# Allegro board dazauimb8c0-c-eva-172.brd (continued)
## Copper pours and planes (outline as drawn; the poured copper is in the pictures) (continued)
GND on IN1 (solid shape): outline of 260 points within 0.25,18.86 15.33,29.65
GND on IN1 (solid shape): outline of 1575 points within 0.25,0.25 219.55,127.75
GND on IN2 (solid shape): 102.8,87.87 102.8,85.58 102.68,85.46 98.99,85.46 98.87,85.58 98.87,86.85 98.11,87.62 98.11,88.25 98.27,88.42 102.26,88.42
GND on IN2 (solid shape): 27.16,72.69 27.16,70.36 27.01,70.2 26.97,70.2 26.5,70.2 26.39,70.32 26.39,72.76 27.1,72.76
GND on IN2 (solid shape): 100.64,26.62 100.64,26.16 100.13,25.66 100.13,25.65 99.99,25.51 99.99,25 99.84,24.85 97.3,24.85 96.93,25.22 96.93,25.72 97.51,26.3 97.51,26.38 97.56,26.44 97.56,26.75 97.66,26.84 100.12,26.84 100.16,26.88 100.37,26.88
GND on IN2 (solid shape): 49.18,98.59 49.29,98.61 49.35,98.52 49.35,97.53 49.06,97.24 44.86,97.24 44.76,97.31 44.79,97.42 45.14,97.78 48.36,97.78
GND on IN2 (solid shape): 22.01,69.96 22.01,66.36 19.29,63.64 16.11,63.64 15.3,62.83 15.3,60.54 14.82,60.06 13.67,60.06 13.27,59.65 13.27,59.24 12.5,59.24 12.5,61.84 11.88,62.58 11.04,62.09 8.9,62.09 8.54,61.95 8.4,61.59 8.4,61.49 2.21,61.49 1.85,61.85 1.85,67.89 2.21,68.25 7.07,68.25 8.33,67.35 9.35,68.5 9.35,70.8 9.49,70.93 9.74,70.93 9.82,70.85 9.82,70.27 10.15,69.94 12.91,69.94 15.66,72.68 19.29,72.68
GND on IN2 (solid shape): 12.42,89.2 12.37,88.88 12.25,88.59 12.25,87.74 12.71,87.28 12.71,83.2 12.03,82.51 10.63,82.51 9.97,81.85 9.43,81.85 9.35,81.93 9.35,83.9 8.33,85.05 7.07,84.15 2.11,84.15 1.75,84.51 1.75,87.15 0.25,87.15 0.25,88.4 0.61,88.75 4.75,88.75 4.75,88 4.88,87.68 5.2,87.55 6.6,87.55 6.92,87.68 7.05,88 7.05,88.75 11.2,88.75 11.52,88.88 11.65,89.2 11.65,89.6 12.42,89.6
GND on IN2 (solid shape): 13.27,49.39 14.08,48.58 14.72,48.58 15.07,48.22 15.07,47.64 14.67,47.23 13.65,47.23 13.24,46.82 13.24,45.33 14.73,43.84 14.73,42.51 15.3,41.94 15.3,40.27 15.05,40.02 13.54,40.02 13.27,39.74 13.27,39.25 12.5,39.25 12.5,41.84 11.88,42.58 11.04,42.09 8.9,42.09 8.54,41.95 8.4,41.59 8.4,41.49 3.35,41.49 2.99,41.85 2.99,47.03 3.35,47.39 8.4,47.39 8.4,47.29 8.54,46.93 8.9,46.79 11.04,46.79 11.88,46.3 12.5,47.04 12.5,49.62 13.27,49.62
GND on IN2 (solid shape): 10.37,113.92 10.43,113.83 10.43,113.55 10.73,113.24 13.17,113.24 15.48,110.93 15.48,107.4 12.38,104.3 12.38,103.5 12.41,103.35 12.42,103.2 12.42,102.5 11.65,102.5 11.65,103.2 11.52,103.52 11.2,103.65 7.05,103.65 7.05,104.4 6.92,104.72 6.6,104.85 5.2,104.85 4.88,104.72 4.75,104.4 4.75,103.65 0.61,103.65 0.25,104.01 0.25,105.29 0.41,105.45 1.85,105.45 1.85,110.95 0.41,110.95 0.25,111.11 0.25,112.69 0.61,113.05 3.35,113.05 3.41,113.03 3.69,112.81 3.97,112.75 5.93,112.75 6.22,112.82 6.5,113.05 7.44,113.08 7.45,113.05 8.34,112.73 8.62,113.64 8.62,113.75 8.72,113.79 8.78,113.78 8.84,113.78 9.86,113.78 10.07,113.81 10.26,113.91
GND on IN2 (solid shape): 46.78,105.13 46.78,103.72 47.83,102.68 47.83,102.38 47.78,102.3 47.69,102.29 47.63,102.3 47.56,102.31 47.3,102.2 47.19,101.94 47.22,101.81 47.29,101.69 47.31,101.62 47.29,101.56 47.22,101.44 47.19,101.31 47.3,101.05 47.56,100.94 47.65,100.95 47.76,100.99 47.81,100.98 47.83,100.94 47.83,100.9 47.23,100.3 46.3,100.3 46.22,100.35 46.21,100.45 46.24,100.53 46.25,100.62 46.17,100.85 45.96,100.98 45.9,101.03 45.88,101.11 45.89,101.16 45.9,101.2 45.89,101.26 45.88,101.33 45.88,101.58 45.91,101.61 45.98,101.64 46.05,101.62 46.16,101.55 46.29,101.53 46.56,101.63 46.66,101.9 46.6,102.09 46.45,102.23 46.39,102.3 46.42,102.39 46.58,102.56 46.58,105 46.66,105.08 46.66,105.09 46.72,105.16
GND on IN2 (solid shape): outline of 173 points within 48.13,101.58 51.72,104.62
GND on IN2 (solid shape): outline of 260 points within 0.25,18.86 15.28,29.65
GND on IN2 (solid shape): outline of 1570 points within 0.25,0.25 219.55,127.75
GND on IN2 (solid shape): outline of 29993 points within 28.68,30.44 80.96,95.39
GND on SVCC (solid shape): 218.28,51.43 217.55,50.87 217.28,50 217.28,48.84 216.81,48.37 216.32,48.37 215.96,48.73 215.96,49.64 215.94,49.74 215.89,49.82 215.38,50.33 215.3,50.39 215.2,50.41 212.89,50.41 212.79,50.51 212.79,50.79 212.78,50.84 214.4,53.59 215.76,56.48 218.28,56.48
GND on SVCC (solid shape): 7.57,46.12 8.17,45.67 8.9,45.52 10.42,45.52 11.04,45.15 11.75,45.02 11.75,43.86 11.04,43.73 10.42,43.36 8.9,43.36 8.17,43.21 7.57,42.76 4.64,42.76 4.26,43.14 4.26,45.63 4.75,46.12
GND on SVCC (solid shape): 123.18,126.4 123.77,124.97 125.2,124.38 131.2,124.38 132.63,124.97 133.22,126.4 133.22,126.48 143.48,126.48 143.48,124.99 143.42,124.9 143.32,124.9 142.93,125.07 142.5,125.13 141.35,124.65 140.87,123.5 141.35,122.35 142.5,121.87 142.93,121.93 143.32,122.1 143.42,122.1 143.48,122.01 143.48,81.78 143.21,81.52 142.13,81.52 142.03,81.57 141.92,81.58 141.82,81.57 141.73,81.53 141.71,81.52 141.59,81.52 141.58,81.55 141.44,81.72 141.24,81.79 141.03,81.72 140.89,81.55 140.88,81.52 126.41,81.52 123.51,84.42 123.51,85.58 123.49,85.68 123.43,85.76 121.02,88.18 120.94,88.23 120.84,88.25 111.55,88.25 110.04,89.75 110.04,91.05 110.02,91.14 109.97,91.22 107.96,93.24 107.95,93.26 107.86,93.44 107.68,93.53 107.66,93.53 106.62,94.58 106.62,95.8 106.62,95.85 106.62,95.91 106.62,96.29 107.08,96.76 109.54,96.76 109.63,96.78 109.72,96.83 110.1,97.22 110.15,97.3 110.17,97.4 110.17,114.05 114.92,118.81 114.98,118.89 115,118.99 115,125.86 115.61,126.48 123.18,126.48
GND on SVCC (solid shape): outline of 145 points within 26.61,34.28 82.74,96.38
GND on IN3 (solid shape): 65.85,37.19 65.85,34.53 65.71,34.4 65.71,33.88 63.94,33.88 63.94,37.32 65.72,37.32
GND on IN3 (solid shape): 100.77,26.91 100.77,26.15 100.26,25.64 100.26,24.88 100.14,24.75 97.47,24.75 97.09,25.13 97.09,27.04 97.34,27.29 100.39,27.29
GND on IN3 (solid shape): 102.8,88.12 102.8,85.46 102.55,85.2 98.99,85.2 98.87,85.33 98.87,86.98 98.23,87.62 98.23,88.12 98.49,88.38 102.55,88.38
GND on IN3 (solid shape): 45.73,113.78 45.73,112.46 45.63,112.36 44,112.36 43.8,112.56 43.8,113.37 43.7,113.47 43.09,113.47 42.99,113.57 42.99,113.78 43.09,113.88 45.63,113.88
GND on IN3 (solid shape): 12.42,89.2 12.37,88.88 12.25,88.59 12.25,87.74 12.71,87.28 12.71,83.2 12.03,82.51 10.63,82.51 9.94,81.82 9.51,81.82 9.35,81.98 9.35,83.9 8.33,85.05 7.07,84.15 2.11,84.15 1.75,84.51 1.75,87.15 0.25,87.15 0.25,88.4 0.61,88.75 4.73,88.75 4.75,88.73 4.75,88 4.88,87.68 5.2,87.55 6.6,87.55 6.92,87.68 7.05,88 7.05,88.75 11.2,88.75 11.52,88.88 11.65,89.2 11.65,89.6 12.42,89.6
GND on IN3 (solid shape): 13.27,49.39 14.08,48.58 14.72,48.58 15.07,48.22 15.07,47.64 14.67,47.23 13.65,47.23 13.52,47.1 13.52,45.58 14.08,45.02 14.08,42.35 15.3,41.13 15.3,40.27 15.05,40.02 13.54,40.02 13.27,39.74 13.27,39.25 12.5,39.25 12.5,41.84 11.88,42.58 11.04,42.09 8.9,42.09 8.54,41.95 8.4,41.59 8.4,41.49 3.35,41.49 2.99,41.85 2.99,47.03 3.35,47.39 8.4,47.39 8.4,47.29 8.54,46.93 8.9,46.79 11.04,46.79 11.88,46.3 12.5,47.04 12.5,49.62 13.27,49.62
GND on IN3 (solid shape): 21.53,69.8 21.59,69.64 21.64,69.47 21.64,66.83 21.61,66.74 21.58,66.65 18.98,64.05 18.7,63.95 18.4,63.88 16.36,63.88 15.3,62.83 15.3,60.54 14.82,60.06 13.67,60.06 13.27,59.65 13.27,59.24 12.5,59.24 12.5,61.84 11.88,62.58 11.04,62.09 8.9,62.09 8.54,61.95 8.4,61.59 8.4,61.49 2.21,61.49 1.85,61.85 1.85,67.89 2.21,68.25 7.07,68.25 8.33,67.35 9.35,68.5 9.35,70.85 9.46,70.95 9.74,70.95 9.82,70.88 9.82,70.27 10.15,69.94 13.58,69.94 15.65,72.01 19.31,72.01
GND on IN3 (solid shape): 10.73,113.24 13.17,113.24 15.48,110.93 15.48,107.4 12.38,104.3 12.38,103.5 12.41,103.35 12.42,103.2 12.42,102.5 11.65,102.5 11.65,103.2 11.52,103.52 11.2,103.65 7.05,103.65 7.05,104.4 6.92,104.72 6.6,104.85 5.2,104.85 4.88,104.72 4.75,104.4 4.75,103.65 0.61,103.65 0.25,104.01 0.25,105.29 0.41,105.45 1.85,105.45 1.85,110.95 0.41,110.95 0.25,111.11 0.25,112.69 0.61,113.05 3.35,113.05 3.41,113.03 3.69,112.81 3.97,112.75 5.93,112.75 6.22,112.82 6.5,113.05 7.44,113.08 7.45,113.05 8.19,112.67 8.7,113.33 8.89,113.51 10.46,113.51
GND on IN3 (solid shape): outline of 260 points within 0.25,18.86 15.33,29.65
GND on IN3 (solid shape): outline of 1592 points within 0.25,0.25 219.55,127.75
GND on SGND1 (solid shape): outline of 2645 points within 0.51,0.51 219.29,127.49
V3A_BOOT on BOTTOM (solid shape): 147.51,32.93 147.51,32.63 147.18,32.29 147.18,31.94 147.15,31.91 147.13,31.91 147.1,31.89 146.39,31.89 146.34,31.94 146.34,32.22 146.42,32.29 146.57,32.29 146.72,32.45 146.72,32.93 146.77,32.98 147.46,32.98
VCC1P8A on TOP (solid shape): outline of 383 points within 93.55,51.37 108.8,58.08
VCCPLL_OC_DIS2 on TOP (solid shape): 52.51,30.47 52.51,29.7 52.39,29.57 52.39,29.34 52.33,29.25 52.23,29.25 51.74,29.17 51.78,28.67 51.81,28.6 51.78,28.52 51.65,28.39 51.65,28.22 51.6,28.13 51.5,28.13 51.37,28.25 51.19,28.3 50.99,28.24 50.86,28.08 50.84,28.05 49.67,28.05 49.5,28.22 49.5,28.6 49.92,29.02 50.2,29.02 50.61,29.42 50.61,30.59 50.73,30.72 52.26,30.72
VCCSTPLL_DIS2 on BOTTOM (solid shape): 112.74,59.65 112.74,58.81 112.71,58.79 112.08,58.79 111.62,58.33 111.55,58.32 111.48,58.3 110.44,58.3 110.41,58.28 110.35,58.28 110.35,59.63 111.89,59.63 111.95,59.6 112.05,59.59 112.15,59.6 112.2,59.6 112.3,59.7 112.69,59.7
VDDQ_SW on TOP (solid shape): 59.77,124.12 59.77,123.66 60.75,122.69 60.75,122.61 62.16,121.2 64.8,121.2 64.86,121.14 64.86,120.97 64.84,120.95 63.61,120.95 63.35,120.68 61.92,120.68 61.87,120.69 61.83,120.69 61.79,120.69 61.74,120.68 61.57,120.68 61.48,120.59 57.36,120.59 57.21,120.74 57.21,123.94 57.45,124.19 59.7,124.19
VDDQ_SW on BOTTOM (solid shape): 61.54,121.68 61.54,120.66 61.38,120.51 60.71,120.51 60.4,120.82 60.4,121.04 60.21,121.23 59.76,121.23 59.67,121.32 59.67,122.15 60.1,122.58 60.65,122.58
VDDQ_SW_VPP on TOP (solid shape): 63.31,125.68 63.31,123.59 63.19,123.47 63.19,122.74 63.14,122.74 63.14,122.2 63.12,122.18 62.43,122.18 62.16,122.44 62.16,123.21 62.15,123.22 62.15,125.7 63.28,125.7
VDDQ_VCC on TOP (solid shape): 67.39,125.06 67.39,124.4 67,124.01 66.46,124.01 66.18,123.73 64.54,123.73 64.26,123.45 64.26,122.74 64.14,122.74 64.14,122.17 63.89,122.17 63.89,122.74 63.64,122.74 63.64,122.17 63.41,122.17 63.39,122.18 63.39,122.74 63.35,122.74 63.35,123.25 63.54,123.44 63.54,124.4 63.73,124.58 66.45,124.58 67,125.13 67.32,125.13
VDDQ_VLDOIN on TOP (solid shape): 61.62,119.93 62.05,119.93 62.14,120.02 63.04,120.02 63.1,119.96 63.1,119.36 62.94,119.19 62.29,119.19 62.25,119.2 62.21,119.2 62.17,119.2 62.13,119.19 62,119.19 61.73,118.93 61.73,118.03 61.6,117.89 61.17,117.89 60.79,118.27 60.79,119.83 60.98,120.02 61.53,120.02
VDDQ_VTT on TOP (solid shape): 63.64,119.9 63.64,119.34 63.67,119.34 63.67,119.02 63.54,118.89 63.54,118.73 63.38,118.57 63.38,118 63.29,117.91 62.95,117.91 62.84,118.02 62.84,118.85 63.33,119.34 63.39,119.34 63.39,119.92 63.62,119.92
VDDQ_VTT on BOTTOM (solid shape): 64.19,121.41 64.19,120.35 63.99,120.14 63.99,119.39 63.6,119 63.6,118.65 63.55,118.59 62.86,118.59 62.86,120.33 63.14,120.6 63.14,121.24 63.14,121.24 63.41,121.51 64.09,121.51
5213LX_1.8V on TOP (solid shape): 40.02,32.02 40.02,31.63 39.84,31.46 39.74,31.46 39.56,31.28 39.56,30.69 39.48,30.62 39.48,30.29 39.51,30.26 39.51,30.1 39.52,30.07 39.53,30.03 39.64,30.03 39.64,30.03 40.53,30.03 40.53,30.02 40.53,29.73 40.35,29.73 40.35,29.73 39.58,29.73 39.18,29.32 39.18,28.82 38.67,28.31 38.03,28.31 37.91,28.43 37.91,31.86 38.16,32.12 39.91,32.12
8813BOOT1 on TOP (solid shape): 77.94,114.54 77.97,114.53 77.99,114.49 77.99,113.96 77.97,113.92 77.94,113.91 77.48,113.91 75.91,112.33 75.2,112.33 75.09,112.43 75.09,113.12 75.14,113.17 75.83,113.17 77.2,114.54
8813BOOT2 on TOP (solid shape): 76.97,108.32 78.29,108.32 78.42,108.19 78.42,107.56 78.29,107.43 78.22,107.43 77.63,107.43 77.59,107.43 76.52,107.43 75.55,108.39 75.09,108.39 75.08,108.41 75.08,109.09 75.21,109.22 76.07,109.22
8813LGAT1 on TOP (solid shape): 77.94,112.03 77.94,111.62 77.71,111.39 75.6,111.39 75.57,111.41 75.55,111.44 75.55,111.63 75.57,111.67 75.6,111.68 76.37,111.68 76.37,111.7 76.44,111.7 77.05,112.3 77.66,112.3
8813LGAT1 on BOTTOM (solid shape): 77.33,117.33 77.33,116.7 77.31,116.66 77.28,116.65 76.8,116.65 76.41,116.27 76.41,116.14 76.24,115.96 75.35,115.96 75.3,115.91 75.3,115.61 75.25,115.56 74.84,115.56 74.76,115.63 74.76,116.19 75.04,116.47 75.04,117.56 75.14,117.66 77,117.66
8813LGAT2 on BOTTOM (solid shape): 84.06,110.02 84.06,109.66 84.02,109.57 84.01,109.46 84.02,109.35 84.06,109.26 84.06,107.83 83.98,107.76 83.32,107.76 83.22,107.86 83.22,110.1 83.42,110.3 83.78,110.3
8813PHASE1 on TOP (solid shape): 77.96,113.22 78,113.2 78.01,113.17 78.01,112.56 77.99,112.53 77.02,112.53 76.39,111.9 75.6,111.9 75.57,111.91 75.55,111.95 75.55,112.08 75.65,112.18 75.93,112.18 75.96,112.2 76.98,113.22
8813PHASE1 on BOTTOM (solid shape): 79.79,121.98 79.79,117.66 79.54,117.41 77.76,117.41 77.1,118.07 76.29,118.07 75.96,118.4 75.96,121.25 76.8,122.08 79.69,122.08
8813PHASE2 on TOP (solid shape): 76.46,109.66 76.72,109.66 76.92,109.46 77.36,109.46 78.29,109.46 78.42,109.33 78.42,108.83 78.29,108.7 76.8,108.7 76.11,109.38 75.65,109.38 75.55,109.49 75.55,109.59 75.63,109.66 76.46,109.66
8813PHASE2 on BOTTOM (solid shape): 82.62,114.81 82.62,110.82 82.84,110.6 82.84,108.98 82.71,108.85 79.56,108.85 79.39,109.03 79.39,110.16 79.59,110.36 79.59,110.68 79.39,110.88 79.39,110.98 79.52,111.11 79.57,111.3 79.52,111.48 79.39,111.62 79.39,114.63 79.7,114.94 82.5,114.94
8813UGATE1 on BOTTOM (solid shape): 72.91,116.16 72.96,116.15 73.01,116.16 73.06,116.17 73.54,116.17 73.67,116.04 73.67,115.63 73.94,115.37 74.65,115.37 75.2,114.82 75.2,114.21 75.09,114.11 73.98,114.11 73.95,114.13 73.28,114.13 72.68,114.73 72.68,116.06 72.78,116.17 72.86,116.17
8813UGATE1_1 on BOTTOM (solid shape): 71.31,117.59 71.31,116.85 71.41,116.75 71.41,116.55 71.51,116.45 71.55,116.4 71.59,116.37 71.66,116.29 71.84,116.29 72.07,116.29 72.2,116.17 72.2,115.33 72.1,115.23 71.33,115.23 71.13,115.43 71.13,115.58 70.98,115.73 70.94,115.78 70.9,115.81 70.7,116.01 70.7,116.32 70.57,116.45 70.12,116.45 69.99,116.57 69.99,116.93 70.09,117.03 70.42,117.03 70.7,117.31 70.7,117.59 70.72,117.61 71.28,117.61
8813UGATE2 on TOP (solid shape): 74.81,109.23 74.85,109.22 74.86,109.18 74.86,108.34 74.97,108.24 75.37,108.24 77.07,106.54 77.91,106.54 78.04,106.41 78.04,105.52 77.91,105.4 77.02,105.4 75.12,107.3 75.12,107.68 74.56,108.24 74.56,108.39 74.57,108.39 74.57,109.18 74.59,109.22 74.62,109.23
8813UGATE2_1 on BOTTOM (solid shape): 84.75,104.53 84.75,103.87 84.21,103.34 84.17,103.34 84.17,103.34 83.37,103.34 83.34,103.35 83.32,103.39 83.32,103.97 83.37,104.02 83.86,104.02 84.01,104.02 84.01,104.17 84.14,104.3 84.14,104.58 84.15,104.62 84.19,104.63 84.64,104.63
24780_BST on BOTTOM (solid shape): 130.79,30.19 130.79,30.18 130.84,30.13 130.84,30.12 130.99,29.97 131.71,29.97 131.74,30 132.57,30 132.61,29.98 132.62,29.95 132.62,29.82 132.61,29.81 131.76,29.81 131.7,29.75 131.52,29.75 131.51,29.73 131.38,29.74 131.14,29.74 130.8,29.4 130.15,29.4 130.12,29.41 130.1,29.45 130.1,30.17 130.12,30.2 130.15,30.22 130.76,30.22
24780_LX on BOTTOM (solid shape): 125.61,31.63 125.61,31.21 125.35,30.95 125.35,27.44 125.21,27.3 122.8,27.3 122.41,26.91 122.41,25.82 122.39,25.79 121.68,25.79 121.65,25.82 121.65,27.14 121.5,27.29 119.07,27.29 118.51,27.85 118.51,30.27 119.23,30.99 123.66,30.99 123.77,31.1 123.77,31.69 123.86,31.78 125.46,31.78
24780_LX on BOTTOM (solid shape): 131.14,31.67 131.17,31.66 131.19,31.64 131.27,31.53 131.39,31.46 131.4,31.45 131.69,31.16 131.69,30.88 131.76,30.81 131.82,30.81 131.82,30.81 132.57,30.81 132.61,30.79 132.62,30.76 132.62,30.62 132.62,30.61 131.6,30.61 131.6,30.62 131.4,30.81 130.11,30.81 130.07,30.83 130.06,30.86 130.06,31.62 130.07,31.66 130.11,31.67
24780_VCC on BOTTOM (solid shape): 130.95,33.41 130.95,32.95 131.13,32.77 132.62,31.28 132.62,31.06 132.6,31.02 132.57,31.01 131.87,31.01 131.84,31.02 131.82,31.06 131.82,31.21 130.98,32.05 130.61,32.05 130.08,32.57 130.08,33.49 130.11,33.51 130.85,33.51
+1.03_GFX on BOTTOM (solid shape): 119.19,123.18 119.19,122.13 118.93,121.88 118.93,119.11 118.81,118.99 118.47,118.99 118.46,118.99 117.91,118.99 117.26,119.65 117.26,121.86 117.66,122.26 117.66,122.92 118.04,123.3 119.06,123.3
+1.03_GFX on BOTTOM (solid shape): 71.56,105.52 72.58,105.52 72.76,105.35 72.76,102.93 72.88,102.81 72.88,102.02 72.58,102.02 72.25,101.69 72.25,101.18 72.15,101.08 71.05,101.08 70.93,101.2 70.93,105.12 70.93,105.52 71.05,105.65 71.44,105.65
+1.03_GFX on IN1 (solid shape): outline of 337 points within 66.15,104.43 72.96,118.22
+1.03_GFX on IN1 (solid shape): outline of 602 points within 94.42,121.4 118.93,125.97
+1.03_GFX on IN2 (solid shape): outline of 619 points within 109.41,108.57 118.81,123.68
+601_VCC on TOP (solid shape): 216.09,16.75 216.09,16.62 215.96,16.5 214.06,16.5 213.98,16.57 213.95,16.65 213.98,16.72 214.08,16.85 214.11,17 214,17.27 213.73,17.39 213.57,17.35 213.44,17.26 213.37,17.23 213.29,17.26 212.41,17.26 212.28,17.39 212.28,17.88 212.4,18.06 212.44,18.27 212.44,18.41 212.46,18.43 214.41,18.43
+601_VCC on TOP (solid shape): 204.91,19.04 204.91,18.4 204.38,17.87 204.38,12.71 204.62,12.47 205.32,11.77 205.85,11.77 205.98,11.64 206.46,11.64 206.54,11.61 206.64,11.59 206.74,11.59 206.76,11.61 206.77,11.62 206.89,11.7 206.97,11.82 206.97,11.83 207.33,12.18 207.33,13.02 207.63,13.32 207.63,13.64 207.67,13.73 207.68,13.83 207.68,13.89 207.66,13.96 207.67,14.05 207.75,14.1 207.77,14.1 207.92,14.25 207.96,14.25 208.2,14.35 208.3,14.59 208.27,14.74 208.18,14.86 208.14,14.93 208.16,15 208.21,15.07 208.23,15.16 208.24,15.17 208.55,15.48 209.36,15.48 209.48,15.35 209.48,15.23 209.26,15 209.26,14.31 208.47,13.52 208.47,12.5 208.46,12.5 208.46,11.92 207.88,11.34 207.88,10.6 207.83,10.55 206.03,10.55 205.6,10.98 205.6,11.03 205.31,11.32 204.76,11.32 204.64,11.44 204.63,11.44 204.58,11.49 204.58,11.73 203.54,12.77 203.54,17.51 203.54,18.3 204.4,19.16 204.79,19.16
+601_VCC on IN2 (solid shape): outline of 165 points within 207.07,11.5 215.83,18.02
+AZA_VDD on BOTTOM (solid shape): 211.26,26.83 211.26,26.12 210.96,25.82 210.96,25.06 210.22,25.06 210.12,25.16 210.12,26.76 210.2,26.83 210.2,27.34 210.22,27.37 210.73,27.37
+FB_PLLAVDD on IN2 (solid shape): outline of 95 points within 106.51,97.4 112.39,98.96
+SMDDR_VREF_DQ1_M1 on TOP (solid shape): 49.45,99.18 49.49,99.18 49.54,99.16 50.6,99.16 50.63,99.17 50.67,99.17 50.85,99.1 50.92,98.92 50.9,98.82 50.85,98.74 50.84,98.73 50.76,98.68 50.66,98.66 49.46,98.66 49.42,98.66 49.37,98.67 45.23,98.67 44.87,98.31 44.87,96.71 44.79,96.63 44.28,96.63 44.23,96.58 44.23,93.89 44.13,93.79 43.78,93.79 43.72,93.84 43.72,96.71 44.33,97.32 44.33,97.6 44.36,97.62 44.36,98.53 45.02,99.18
+TYPEC_VBUS on TOP (solid shape): 14.92,16.35 15.17,16.09 16.69,16.09 16.81,15.97 16.81,14.4 16.72,14.31 16.22,14.31 16.06,14.46 15.3,14.46 15.29,14.45 15.07,14.45 14.94,14.32 14.94,14.14 14.92,14.12 14.92,13.45 14.67,13.19 13.14,13.19 12.89,13.45 12.89,13.56 12.9,13.58 12.98,13.69 13,13.83 12.98,13.96 12.92,14.07 12.9,14.1 12.92,14.14 13.03,14.29 13.07,14.46 13.06,14.51 13.45,14.9 13.48,14.88 13.57,14.85 13.65,14.84 13.92,14.96 14.03,15.23 14.01,15.36 13.94,15.48 13.91,15.54 13.94,15.61 14.01,15.73 14.03,15.86 14.01,15.99 13.95,16.1 13.92,16.13 14.16,16.37 14.92,16.37
+TYPEC_VBUS on TOP (solid shape): outline of 111 points within 11.87,7.03 14.36,11.67
+TYPEC_VBUS on BOTTOM (solid shape): 6.82,17.28 6.83,17.28 7.5,17.28 7.52,17.26 7.52,17.03 7.51,17.02 6.43,17.02 6.28,16.88 5.9,16.88 5.78,17 5.78,17.54 5.88,17.64 6.46,17.64
+TYPEC_VBUS on BOTTOM (solid shape): 6.85,14.78 7.5,14.78 7.5,14.77 7.5,14.53 7.5,14.52 6.88,14.52 6.59,14.24 5.9,14.24 5.83,14.31 5.83,14.74 6.01,14.92 6.71,14.92
+TYPEC_VBUS on BOTTOM (solid shape): 16.11,17.36 16.11,14.01 15.43,13.32 14.03,13.32 13.24,12.53 13.04,12.53 12.89,12.69 12.89,13.19 12.89,13.19 12.89,13.55 12.98,13.67 13.02,13.83 12.99,13.96 12.92,14.08 12.9,14.15 12.92,14.21 13,14.34 13.02,14.59 13.02,14.85 13.18,15.01 13.26,15.01 13.35,14.92 13.95,14.91 13.98,15.51 13.96,15.54 13.98,15.58 14.08,15.91 13.9,16.21 13.9,17.26 14.08,17.44 16.04,17.44
+TYPEC_VBUS on IN2 (solid shape): outline of 1536 points within 6.12,7.48 17.1,19.67
+TYPEC_VBUS_C on TOP (solid shape): 19.56,18.33 19.45,18.2 19.41,18.03 19.51,17.78 19.75,17.66 19.75,13.7 19.42,13.38 17.55,13.38 17.1,13.83 17.1,18.16 17.33,18.4 19.49,18.4
+TYPEC_VBUS_C on BOTTOM (solid shape): outline of 124 points within 16.43,15.02 23.75,18.27
+USBPWR0 on TOP (solid shape): 19.49,51.99 19.49,49.77 18.22,49.77 18.1,49.9 17.59,49.9 17.16,50.33 17.16,51.93 17.47,52.25 19.24,52.25
+USBPWR0 on BOTTOM (solid shape): outline of 508 points within 13.9,49.14 23.05,58.79
+USBPWR1 on TOP (solid shape): 15.96,47.66 15.96,45.78 15.5,45.32 15.5,42.91 16.65,41.77 16.65,38.34 16.7,38.29 16.7,37.96 16.06,37.32 15.28,37.32 15.23,37.38 14.36,37.38 13.9,37.83 13.9,38.59 15.56,40.25 15.56,41.26 14.41,42.4 14.41,46.85 14.81,47.24 14.84,47.24 14.93,47.33 15.21,47.52 15.38,47.81 15.43,47.87 15.76,47.87
+USBPWR1 on BOTTOM (solid shape): outline of 316 points within 13.9,37.2 22.54,48.88
+USBPWR1 on IN3 (solid shape): 16.57,47.61 16.57,46.21 15.94,45.58 15.94,43.04 16.19,42.79 17.64,42.79 17.9,42.52 17.9,40.3 17.97,40.23 17.97,40.12 17.33,39.48 17.33,38.72 15.81,37.2 14.29,37.2 13.9,37.58 13.9,38.34 15.56,39.99 15.56,41.13 14.29,42.4 14.29,46.47 14.92,47.1 14.92,47.32 14.93,47.33 15.23,47.54 15.39,47.87 16.32,47.87
+VGPU_CORE on TOP (solid shape): 86.17,122.16 86.17,120.82 86.82,120.17 86.82,119.53 86.78,119.37 86.82,119.2 86.82,118.34 86.17,117.69 86.17,117.23 85.83,116.89 81.36,116.89 80.99,117.26 80.99,119.27 81.85,120.13 81.85,122.67 82.23,123.05 85.28,123.05
+VGPU_CORE on TOP (solid shape): 104.54,102 104.8,101.74 104.81,101.73 104.89,101.63 105.02,101.59 105.12,101.59 105.2,101.56 105.22,101.48 105.22,101.43 105.29,101.22 105.48,101.09 105.49,101.09 105.62,100.95 105.62,100.87 105.61,100.84 105.57,100.82 105.51,100.76 105.51,100.65 105.4,100.55 104.92,100.55 104.12,101.34 104.11,101.38 104.12,101.41 104.32,101.61 104.32,101.61 104.42,101.7 104.45,101.82 104.45,101.96 104.47,101.99 104.5,102.01
+VGPU_CORE on TOP (solid shape): outline of 2024 points within 97.5,100.82 116.77,125.18
+VGPU_CORE on BOTTOM (solid shape): outline of 102 points within 103.95,114.79 116.39,125.84
+VGPU_CORE on BOTTOM (solid shape): outline of 131 points within 80.96,106.54 89.72,122.67
+VGPU_CORE on IN1 (solid shape): outline of 92 points within 80.17,109.36 89.76,119.71
+VGPU_CORE on IN2 (solid shape): outline of 5457 points within 80.61,98.79 113.09,123.61
+VGPU_CORE on SVCC (solid shape): 114.49,125.86 114.49,119.09 109.74,114.34 109.68,114.26 109.66,114.16 109.66,97.5 109.43,97.27 101.77,97.27 101.64,97.4 101.65,97.44 101.65,97.48 101.56,97.72 101.28,97.81 101.24,97.8 98.3,100.73 98.31,100.78 98.32,100.83 98.22,101.07 97.97,101.17 97.93,101.17 97.88,101.16 90.6,108.43 90.61,108.49 90.5,108.76 90.24,108.86 90.18,108.86 89.27,109.77 89.19,109.82 89.09,109.84 85.64,109.84 80.03,115.45 80.03,115.49 80.03,115.53 79.93,115.79 79.67,115.9 79.63,115.9 79.59,115.89 78.95,116.53 78.95,124.09 79.24,124.38 85.2,124.38 86.63,124.97 87.22,126.4 87.22,126.48 113.88,126.48
+VGPU_CORE on IN3 (solid shape): outline of 142 points within 80.17,108.75 90.41,120.51
+VGPU_CORE on IN3 (solid shape): outline of 3338 points within 99.05,100.7 113.8,123.25
ADOGND on SGND (solid shape): outline of 98 points within 197.8,29.45 216.72,49.9
ADOGND on SVCC (solid shape): outline of 98 points within 197.8,29.45 216.72,49.9
ADOGND on SGND1 (solid shape): outline of 99 points within 197.8,29.45 216.72,49.9
BAT-V on BOTTOM (solid shape): outline of 699 points within 94.3,14.54 113.32,33.74
DIS_VCCSTG1 on BOTTOM (solid shape): 112.33,68.36 112.33,66.99 112.22,66.88 112.19,66.86 110.45,66.86 110.22,67.09 110.22,68.11 110.25,68.13 111.36,68.13 111.75,68.52 112.18,68.52
DIS_VCCSTG2 on BOTTOM (solid shape): 109.66,69.02 109.66,68.49 109.59,68.41 108.55,68.41 108.24,68.11 108.24,67.6 108.16,67.52 107.28,67.52 107.12,67.68 107.12,69.07 107.22,69.18 109.51,69.18
FB_CAL_TERM_GND on BOTTOM (solid shape): 120.36,94.68 120.36,94.02 120.33,93.99 119.95,93.99 119.72,93.76 119.16,93.76 119.09,93.84 119.09,94.58 119.21,94.7 120.33,94.7
FBA_VREFC_1 on TOP (solid shape): 133.84,101.23 133.84,98.92 134.38,98.39 134.38,97.7 134.3,97.62 134.02,97.62 133.89,97.75 133.89,97.98 133.28,98.59 133.28,100.09 133.26,100.11 133.26,101.23 133.39,101.36 133.72,101.36
FBA_VREFC_1 on BOTTOM (solid shape): 134.12,98.64 134.12,97.49 134.1,97.47 134.12,97.45 134.12,97.14 133.92,96.94 133.92,96.17 133.74,95.99 133.74,94.55 133.54,94.35 133.54,93.71 133.28,93.71 133.28,94.73 133.16,94.86 133.16,96.13 133.28,96.25 133.28,96.78 133.48,96.97 133.48,97.47 133.48,97.48 133.48,98.56 133.67,98.74 134.02,98.74
FBA_VREFC_2 on TOP (solid shape): 134.07,105.52 134.07,105.32 133.92,105.17 133.82,105.17 133.28,104.63 133.28,103.82 133.23,103.77 132.93,103.77 132.78,103.92 132.78,104.89 133.56,105.68 133.92,105.68
G5335-AGND-2 on TOP (solid shape): outline of 281 points within 139.46,63 143.62,69.68
G5335-LX-2 on BOTTOM (solid shape): 137.88,71.74 137.88,70.09 137.73,69.94 136.89,69.94 136.69,69.73 136.69,69.65 136.68,69.62 136.68,69.57 136.67,69.52 136.68,69.47 136.69,69.44 136.69,69.08 136.68,69.08 136.68,68.29 136.69,68.29 136.69,68.06 136.79,67.96 137.35,67.96 137.38,67.95 137.39,67.93 137.4,67.91 137.4,65.39 137.17,65.16 137.17,64.38 137.16,64.35 137.15,64.33 136.95,64.33 136.94,64.35 136.93,64.38 136.93,65.08 136.68,65.08 136.68,64.38 136.67,64.35 136.66,64.33 136.46,64.33 136.44,64.35 136.43,64.38 136.43,65.31 136.51,65.39 136.51,67.19 136.41,67.3 136.2,67.3 136.2,67.31 135.38,67.31 135.13,67.56 136.2,67.56 136.2,67.81 135.41,67.81 135.41,67.56 135.13,67.56 134,68.69 134,69.45 134,69.46 134,69.79 134,69.8 134,70.09 133.93,70.16 133.27,70.16 133.03,70.39 133.03,72.53 133.11,72.6 137.02,72.6
G5719LX1.5V on BOTTOM (solid shape): 165.62,24.04 165.7,24.01 165.72,23.93 165.72,23.89 165.77,23.71 165.89,23.59 165.9,23.58 165.92,23.53 165.92,21.96 165.87,21.9 165.81,21.89 165.76,21.87 165.61,21.87 165.56,21.88 165.52,21.88 165.47,21.88 165.42,21.87 165.03,21.87 164.98,21.88 164.93,21.88 164.89,21.88 164.84,21.87 162.88,21.87 162.88,22.82 162.97,22.82 164.06,22.82 164.1,22.82 164.14,22.85 164.27,22.85 164.4,22.97 164.4,23.35 164.58,23.53 164.58,23.85 164.77,24.04
L_SPK+ on TOP (solid shape): 115.16,17.64 115.16,16.47 115.4,16.23 115.4,13.58 115.35,13.52 114.13,13.52 113.92,13.74 113.92,17.61 114.04,17.74 115.06,17.74
L_SPK+ on BOTTOM (solid shape): 210,33.07 210,32.8 209.88,32.68 208.99,32.68 208.95,32.72 207.26,32.72 207.26,32.73 207.26,32.91 207.27,32.93 208.74,32.93 209,33.18 209.89,33.18
L_SPK+ on IN2 (solid shape): 115.44,14.78 115.44,13.66 115.31,13.54 114.27,13.54 114.1,13.71 114.1,14.58 114.36,14.85 115.38,14.85
L_SPK+ on IN2 (solid shape): 210,33.32 210,32.84 209.87,32.71 208.38,32.71 208.27,32.6 208.27,32.04 208.42,31.89 208.42,30.01 208.32,29.91 207.38,29.91 207.17,30.11 207.17,33.08 207.35,33.26 208.65,33.26 208.84,33.45 209.87,33.45
L_SPK+_1 on TOP (solid shape): 116.09,21.25 116.09,20.13 115.1,19.14 115.1,18.32 115,18.22 114.21,18.22 114.08,18.35 114.08,19.47 114.46,19.85 114.46,19.87 114.5,19.88 114.71,20 114.79,20.23 114.73,20.43 114.57,20.56 114.54,20.57 114.54,20.89 114.97,21.32 115.88,21.32 115.89,21.32 116.01,21.32
L_SPK+_1 on BOTTOM (solid shape): 116.6,22.29 116.6,20.86 116.09,20.36 116.09,19.49 115.89,19.29 114.92,19.29 114.82,19.39 114.82,20.27 114.83,20.32 115.5,20.99 115.5,22.24 115.58,22.31 116.57,22.31
L_SPK- on TOP (solid shape): 116.76,17.65 116.76,14.68 116.93,14.51 116.93,13.65 116.8,13.52 115.94,13.52 115.73,13.73 115.73,16.46 115.47,16.72 115.47,17.7 115.52,17.75 116.66,17.75
L_SPK- on BOTTOM (solid shape): 208.95,32.58 209.17,32.58 209.61,32.58 209.7,32.49 209.7,32.21 209.56,32.07 208.72,32.07 208.47,32.32 207.27,32.32 207.26,32.33 207.26,32.5 207.29,32.53 208.25,32.53 208.57,32.53 208.64,32.59 208.94,32.59
L_SPK- on IN2 (solid shape): 209.06,32.58 209.1,32.57 209.15,32.58 209.2,32.59 209.58,32.59 209.66,32.56 209.74,32.55 209.82,32.56 209.9,32.59 211.22,32.59 211.26,32.55 211.26,31.33 211.06,31.13 210.4,31.13 210.12,31.41 210.12,31.81 209.86,32.07 208.67,32.07 208.57,32.17 208.57,32.47 208.68,32.59 209.01,32.59
L_SPK-_1 on TOP (solid shape): 117.11,21.27 117.11,19.61 116.6,19.1 116.6,18.27 116.47,18.15 115.48,18.15 115.4,18.22 115.4,19.01 116.39,20 116.39,21.25 116.47,21.32 117.05,21.32
L_SPK-_1 on BOTTOM (solid shape): 117.64,20.71 117.38,20.46 117.38,19.37 117.26,19.24 116.65,19.24 116.5,19.39 116.5,20.31 116.9,20.71 116.9,22.24 117,22.34 117.64,22.34
MIC2-VREFO on TOP (solid shape): 213.45,44.11 213.45,42.73 213.37,42.66 212.74,42.66 212.38,43.01 212.38,43.39 212.51,43.52 212.51,43.72 212.74,43.95 212.79,43.95 212.99,44.16 213.4,44.16
PBA_PWR on TOP (solid shape): 48.72,21.84 48.96,21.84 49.09,21.71 49.09,21.19 49.14,21.14 49.2,20.98 49.34,20.86 49.34,19.16 48.77,18.6 48.74,18.55 48.68,18.53 47.05,18.53 46.92,18.66 46.92,20.43 47.48,20.99 47.48,21.53 47.81,21.86 48.7,21.86
PBA_PWR_C on BOTTOM (solid shape): 57.08,20.53 57.08,19.21 56.96,19.09 56.83,19.09 56.7,19.21 56.7,19.47 56.5,19.67 54.95,19.67 54.14,20.48 54.14,21.19 56.42,21.19
PBA_PWR_R on TOP (solid shape): 50.66,18.6 50.66,17.55 50.58,17.33 50.66,17.11 50.66,16.8 50.85,16.61 50.85,14.83 50.73,14.72 49.08,14.72 49.03,14.77 49.03,15.28 47.31,17 47.31,18.02 47.56,18.27 48.68,18.27 48.69,18.27 48.91,18.27 49.59,18.96 50.3,18.96
PBA_PWR_R on BOTTOM (solid shape): 53.71,20.15 53.22,19.67 51.6,19.67 51.48,19.79 51.48,20.62 52.06,21.19 53.71,21.19
R_SPK+ on TOP (solid shape): 185.56,15.53 185.56,15.25 185.38,15.07 184.64,15.07 184.41,14.85 184.41,14.39 184.17,14.15 183.41,14.15 183.4,14.16 183.4,15.12 183.62,15.35 184.11,15.35 184.44,15.68 185.41,15.68
R_SPK+ on TOP (solid shape): 119.84,17.5 119.84,15.43 119.82,15.39 119.78,15.38 118.98,15.38 118.49,15.87 118.49,17.54 118.67,17.72 119.62,17.72
R_SPK+ on BOTTOM (solid shape): 208.84,31.33 209,31.33 209.04,31.33 209.98,31.33 210.12,31.19 210.12,30.96 209.98,30.82 209.06,30.82 208.36,31.52 207.28,31.52 207.26,31.54 207.26,31.7 207.29,31.73 208.25,31.73 208.44,31.73
R_SPK+ on IN3 (solid shape): 185.53,15.33 185.91,15.33 185.91,14.39 185.66,14.13 184.29,14.13 183.7,14.72 183.7,15.43 183.91,15.63 185.23,15.63
R_SPK+ on IN3 (solid shape): 210.07,31.26 210.04,31.23 210.04,30.65 209.94,30.55 209.94,30.39 209.76,30.21 208.77,30.21 208.65,30.34 208.65,31.18 208.75,31.28 210.04,31.28
R_SPK+_1 on TOP (solid shape): 119.19,21.04 119.19,19.14 119.19,19.14 119.19,18.22 119.17,18.19 119.14,18.17 118.48,18.17 118.38,18.27 118.38,18.91 118.48,19.01 118.48,21.27 118.53,21.32 118.91,21.32
R_SPK+_1 on BOTTOM (solid shape): 119.66,22.17 119.66,20.31 119.66,19.73 119.31,19.38 119.12,19.38 119.04,19.3 118.67,19.3 118.55,19.42 118.55,19.99 118.57,20.01 118.57,20.25 118.96,20.64 118.96,20.68 118.97,20.69 118.97,22.24 119.03,22.3 119.54,22.3
R_SPK- on TOP (solid shape): 186.55,12.46 186.55,10.83 186.24,10.53 184.34,10.53 183.45,11.42 183.45,11.8 183.83,12.18 185.38,12.18 185.74,12.53 186.47,12.53
R_SPK- on TOP (solid shape): 118.13,17.73 118.17,17.71 118.18,17.68 118.18,15.07 118.26,15.07 118.3,15.06 118.31,15.02 118.31,14.34 117.77,14.34 117.07,15.04 117.07,17.63 117.17,17.73
R_SPK- on BOTTOM (solid shape): 208.69,31.94 209.86,31.94 209.95,31.85 209.95,31.57 209.81,31.43 209.26,31.43 208.91,31.43 208.42,31.92 207.26,31.92 207.26,32.11 207.28,32.13 208.25,32.13 208.5,32.13
R_SPK- on IN3 (solid shape): 187.46,14.36 187.46,13.73 186.47,12.74 186.47,12.15 186.42,12.1 185.87,12.1 185.63,12.33 185.63,12.51 185.43,12.71 185.43,13.09 186.96,14.62 187.21,14.62
R_SPK- on IN3 (solid shape): 209.41,31.96 209.48,31.96 211.16,31.96 211.34,31.79 211.34,30.47 211.26,30.39 210.42,30.39 210.37,30.44 210.37,31.23 210.17,31.43 208.85,31.43 208.75,31.53 208.75,31.89 208.82,31.96
R_SPK-_1 on TOP (solid shape): 117.93,21.31 118.1,21.31 118.13,21.27 118.15,21.27 118.17,21.25 118.17,20.63 118.17,19.14 118.07,19.04 118.07,18.21 118.06,18.17 118.02,18.16 116.97,18.16 116.9,18.22 116.9,18.97 117.41,19.48 117.41,21.22 117.51,21.32 117.92,21.32
R_SPK-_1 on BOTTOM (solid shape): 118.65,22.21 118.65,20.76 118.25,20.36 118.25,19.42 118.07,19.24 117.71,19.24 117.69,19.26 117.69,20.33 117.94,20.59 117.94,20.62 117.96,20.64 117.96,22.27 118.02,22.34 118.53,22.34
RING2 on TOP (solid shape): 214.71,44.89 214.77,44.86 214.85,44.85 215.13,44.85 215.2,44.86 215.27,44.89 215.33,44.89 215.76,44.46 215.98,44.46 216.04,44.39 216.04,44.08 215.94,43.98 215.2,43.98 215.05,43.83 214.82,43.83 214.66,43.98 214.51,43.98 214.21,43.69 213.76,43.69 213.72,43.7 213.71,43.74 213.71,44.26 213.7,44.33 214.26,44.89
RING2 on BOTTOM (solid shape): 215.81,45.15 215.81,44.34 215.72,44.25 212.79,44.25 212.79,44.55 213.85,44.55 214.1,44.55 214.1,44.75 213.85,44.75 212.79,44.75 212.79,45.05 214.1,45.05 214.1,45.25 212.79,45.25 212.79,45.55 214.26,45.55 214.46,45.76 215.2,45.76
RING2 on IN3 (solid shape): 199.6,34.45 199.6,33.44 199.38,33.21 199.38,32.42 199.25,32.29 198.18,32.29 198,32.47 198,32.75 198.51,33.26 198.51,34.48 198.59,34.56 199.5,34.56
RING2 on IN3 (solid shape): 215.56,45.76 215.56,44.59 215.48,44.51 214.51,44.51 214.41,44.53 214.31,44.54 214.24,44.57 214.21,44.64 214.21,45.99 214.23,46.01 215.3,46.01
RT3612_LG1 on BOTTOM (solid shape): 126.11,64.75 126.11,64.02 126.05,63.96 124.3,63.96 124.05,64.2 124.05,65.37 124.18,65.49 125.37,65.49
RT3612_LG2 on BOTTOM (solid shape): 125.4,54.06 126.38,54.06 126.51,53.94 126.51,53.27 126.36,53.12 124.48,53.12 123.86,53.74 123.86,54.06 124.08,54.28 125.18,54.28
RT3612_PHASE1 on BOTTOM (solid shape): 123.76,64.86 123.76,64.13 124.22,63.67 124.87,63.67 125.07,63.47 125.07,60.15 125.06,60.14 125.06,59.68 124.71,59.32 122.56,59.32 122.32,59.09 122.32,58.35 122.04,58.07 121.23,58.07 120.42,58.88 120.42,62.77 120.48,62.84 120.97,62.84 121.02,62.89 121.02,63.05 120.99,63.09 120.76,63.09 120.6,63.25 120.6,64.89 120.9,65.19 123.42,65.19
RT3612_PHASE2 on BOTTOM (solid shape): 122.21,56.15 122.21,55.11 124.36,52.97 125.21,52.97 125.41,52.77 125.41,49.42 125.23,49.25 123.71,49.25 123.43,49.37 123.15,49.25 121.69,49.25 121.09,49.85 121.09,51.29 121.2,51.41 121.3,51.41 121.59,51.41 121.61,51.43 121.61,51.6 121.58,51.63 121.19,51.63 121.09,51.74 121.09,55.96 121.39,56.27 122.09,56.27
RT3612_UG1 on BOTTOM (solid shape): 131.83,62.09 131.83,60.17 131.52,59.85 131.01,59.85 130.86,60 130.86,62.01 131.04,62.2 131.72,62.2
RT3612_UG1_R on BOTTOM (solid shape): 130.6,64.57 130.6,64.38 131.44,63.54 131.71,63.54 131.82,63.43 131.82,62.72 131.79,62.69 131.03,62.69 130.93,62.79 130.93,63.27 130.57,63.64 130.38,63.64 130.06,63.96 129.93,63.96 129.9,63.99 129.9,64.61 129.94,64.65 130.52,64.65
RT3612_UG2_R on BOTTOM (solid shape): 131.53,53.46 131.92,53.46 132.03,53.35 132.03,52.52 131.95,52.43 131.17,52.43 130.93,52.67 130.92,52.7 130.89,52.71 130.42,53.19 130.29,53.19 130.22,53.26 130.22,53.9 130.25,53.94 131.05,53.94
RT6543_LG on BOTTOM (solid shape): 129.93,43.02 129.93,42.63 129.53,42.23 128.36,42.23 128.28,42.3 128.28,42.76 128.68,43.16 129.79,43.16
RT6543_PH on BOTTOM (solid shape): 124.73,48.29 124.73,47.27 125.18,46.81 127.43,46.81 127.68,46.57 127.68,43.89 128.27,43.29 128.27,43.06 127.49,42.28 127.49,42.1 126.79,41.4 126.79,40.8 126.55,40.55 121.59,40.55 119.6,42.55 119.6,45.98 120.44,46.81 123.39,46.81 123.71,47.13 123.71,48.4 123.76,48.45 124.57,48.45
RT6543_UG on BOTTOM (solid shape): 129.64,41.33 129.64,40.67 129.6,40.63 128.8,40.63 128.06,41.37 128.06,41.69 128.23,41.87 129.1,41.87
RT6543_UG on BOTTOM (solid shape): 136.85,41.81 136.85,41.45 136.19,40.79 135.85,40.79 135.72,40.92 135.72,41.69 135.86,41.83 136.83,41.83
RT6543_VCC on BOTTOM (solid shape): 136.31,46.63 136.31,46.61 136.26,46.57 136.26,46 136.31,45.95 136.31,45.43 136.46,45.27 136.46,45.22 137.21,44.48 137.21,43.68 137.06,43.68 136.83,43.45 136.83,43.32 136.76,43.24 136.11,43.24 135.93,43.42 135.93,44.47 135.46,44.94 135.46,46.66 135.49,46.69 136.25,46.69
SLEEVE on TOP (solid shape): 214.96,43.47 215.35,43.47 215.38,43.44 215.38,43.3 215.39,43.25 215.4,43.2 215.4,43.12 215.64,42.89 215.9,42.89 216.02,42.77 216.02,42.31 215.92,42.21 214.07,42.21 213.68,42.61 213.68,43.11 213.75,43.18 214.43,43.18 214.72,43.48 214.96,43.48
SLEEVE on BOTTOM (solid shape): 216.01,43.83 216.01,42.91 215.81,42.7 215.02,42.7 214.85,42.54 214.59,42.54 214.37,42.76 212.84,42.76 212.84,42.76 212.79,42.76 212.79,43.05 214.1,43.05 214.1,43.25 212.79,43.25 212.79,43.55 214.1,43.55 214.1,43.75 212.79,43.75 212.79,44.03 215.81,44.03
SLEEVE on IN3 (solid shape): 201.26,33.59 201.26,32.98 200.47,32.19 199.86,32.19 199.53,32.52 199.53,32.98 200.34,33.79 201.05,33.79
SLEEVE on IN3 (solid shape): 215.5,43.88 215.5,42.94 215.25,42.68 214.29,42.68 213.98,42.99 213.98,43.8 214.18,44 215.38,44
SN_VCORE1 on BOTTOM (solid shape): 124.1,59.14 124.1,58.78 123.52,58.2 122.75,58.2 122.68,58.26 122.68,59.03 122.82,59.16 124.08,59.16
SN_VCORE2 on BOTTOM (solid shape): 124.12,55.76 124.12,55.37 124.06,55.32 122.78,55.32 122.67,55.43 122.67,56.21 122.73,56.27 123.6,56.27
TP_PWR_C on TOP (solid shape): 58.71,108.54 58.73,108.52 58.72,108.48 58.69,108.4 58.68,108.32 58.86,107.99 59.23,107.97 59.26,107.98 59.29,107.96 59.88,107.38 59.88,105.8 60.64,105.04 60.64,104 60.77,103.87 60.77,103.36 60.64,103.24 59.5,103.24 59.42,103.31 58.48,103.31 58.33,103.47 58.33,107.81 58.08,108.06 58.08,108.17 58.48,108.57 58.69,108.57
USBPWRD2 on BOTTOM (solid shape): 214.33,30.47 214.87,30.47 215.09,30.25 215.09,25.93 212.58,23.43 210.63,23.43 210.6,23.46 209.56,23.46 208.82,22.72 208.82,22.66 208.82,22.65 208.78,22.56 208.78,22.39 208.8,22.32 208.81,22.28 208.82,22.22 208.82,22.08 208.57,21.83 207.53,21.83 207.45,21.87 207.44,21.96 207.45,22.02 207.45,22.08 207.45,22.69 207.45,22.87 206.79,23.53 206.79,25.08 206.87,25.16 208.09,25.16 208.11,25.13 209.71,25.13 210.09,24.75 212.2,24.75 212.3,24.85 212.3,25.01 213.04,25.74 213.04,26.88 212.76,27.16 212.76,27.24 212.74,27.26 212.76,27.3 212.79,27.38 212.79,27.54 212.77,27.61 212.77,28.54 212.79,28.55 214.1,28.55 214.1,28.75 212.79,28.75 212.79,29.05 214.1,29.05 214.1,29.25 212.79,29.25 212.79,29.55 214.1,29.55 214.1,29.75 212.79,29.75 212.79,30.05 214.1,30.05 214.1,30.25 212.79,30.25 212.79,30.54 214.26,30.54
VA on TOP (solid shape): 131.02,34.92 131.02,34.78 130.87,34.64 130.87,33.84 130.74,33.72 129.78,33.72 129.63,33.87 129.63,33.9 129.62,33.96 129.6,34.03 129.6,34.94 129.83,35.17 130.77,35.17
VA on TOP (solid shape): outline of 200 points within 8.82,113.02 43.27,122.77
VA on BOTTOM (solid shape): 42,119.14 42,116.57 41.87,116.45 40.32,116.45 40.19,116.57 40.19,119.32 40.22,119.34 41.79,119.34
VA on BOTTOM (solid shape): 12.76,118.48 14.41,116.83 22.16,116.83 22.16,115.81 22.03,115.68 9.86,115.68 9.66,115.88 9.66,117.56 10.14,118.04 11.3,118.04 11.31,117.98 11.32,117.93 11.34,117.87 11.37,117.83 11.4,117.78 11.44,117.74 11.49,117.71 11.54,117.68 11.59,117.67 11.64,117.66 11.7,117.65 11.76,117.66 11.81,117.67 11.86,117.7 11.91,117.73 11.95,117.76 11.99,117.8 12.02,117.85 12.04,117.9 12.06,117.95 12.07,118.01 12.07,118.06 12.06,118.12 12.04,118.17 12.02,118.22 11.99,118.27 11.95,118.31 11.91,118.35 11.86,118.38 11.81,118.4 11.76,118.41 11.7,118.42 11.64,118.42 11.59,118.41 11.54,118.39 11.49,118.36 11.44,118.33 11.4,118.29 11.37,118.25 11.34,118.2 11.32,118.15 11.31,118.09 11.3,118.04 10.14,118.04 10.28,118.17 10.28,118.23 10.31,118.25 10.36,118.3 10.41,118.36 10.45,118.43 10.48,118.49 10.51,118.57 10.52,118.64 10.53,118.71 10.53,118.79 10.52,118.86 10.51,118.93 10.5,118.96 10.52,119.03 10.57,119.16 10.61,119.3 10.63,119.37 12.76,119.37
VA on IN1 (solid shape): outline of 427 points within 9.62,115.05 43.78,122.67
VA on IN2 (solid shape): outline of 402 points within 9.65,115.05 43.75,122.67
VA on SVCC (solid shape): 43.5,123.07 43.5,117.69 42.73,116.92 42.53,116.82 42.43,116.63 40.38,114.57 40.28,114.62 40.17,114.64 39.93,114.55 39.81,114.32 39.4,114.74 39.06,114.97 38.67,115.05 26.22,115.05 25.83,114.97 25.5,114.74 23.52,112.76 22.33,112.76 21.11,113.98 20.78,114.21 20.38,114.29 19.11,114.29 18.72,114.21 18.39,113.98 16.62,112.22 16.4,111.89 16.32,111.49 16.32,111.45 16.17,111.3 15.49,111.3 13.83,113.06 11.5,113.71 11,113.71 10.47,113.68 9.95,113.59 9.94,113.7 9.91,113.8 10.33,114.01 10.51,114.45 10.32,114.91 9.86,115.1 9.57,115.1 9.57,118.09 9.86,118.09 10.33,118.28 10.52,118.75 10.34,119.2 9.91,119.41 9.93,119.48 10.33,119.88 13.06,119.88 13.48,119.46 13.48,119.4 14.07,117.97 15.5,117.38 32.7,117.38 34.13,117.97 34.72,119.4 34.72,123.06 35.04,123.38 43.19,123.38
VA on IN3 (solid shape): outline of 403 points within 9.61,115.05 43.32,122.67
VA2 on TOP (solid shape): 44.66,120.71 44.7,120.7 44.72,120.66 44.72,117.33 44.36,116.98 42.66,116.98 42.48,117.16 42.48,120.46 42.73,120.71
N17047007 on TOP (solid shape): 51.6,118.78 51.6,115.3 51.47,115.18 50.73,115.18 50.61,115.3 50.61,115.68 50.48,115.81 45.27,115.81 45.25,115.84 45.25,120.23 45.4,120.38 49.34,120.38 50,120.38
N17047087 on TOP (solid shape): 118.3,28.13 118.3,28.03 118.29,28.01 118.29,27.49 118.5,27.28 119.19,27.28 119.2,27.28 119.86,27.28 120.05,27.09 120.05,26.25 119.85,26.05 115,26.05 114.25,26.79 114.25,27.07 114.74,27.57 114.74,28.1 115,28.36 118.07,28.36
N17047087 on BOTTOM (solid shape): 117.58,30.92 117.58,28.57 119.01,27.14 119.87,27.14 120.18,26.83 120.18,25.84 119.47,25.13 113.22,25.13 112.96,25.39 111.97,25.39 111.92,25.44 111.92,28.59 112.15,28.82 112.81,28.82 113.09,29.11 113.09,31.11 113.32,31.34 117.16,31.34
N18867651 on TOP (solid shape): 153.7,26.15 153.74,26.13 153.75,26.1 153.75,25.38 153.95,25.38 153.95,26.08 153.96,26.09 154.14,26.09 154.15,26.07 154.15,25.35 154.22,25.28 154.22,25.08 154.39,24.91 154.39,24.59 154.36,24.58 154.16,24.44 154.09,24.22 154.16,23.99 154.36,23.85 154.39,23.84 154.39,23.45 154.38,23.42 154.34,23.4 154.27,23.4 154.11,23.33 154.04,23.17 154.04,22.9 153.91,22.77 151.83,22.77 151.8,22.8 151.8,23.4 151.95,23.56 152.1,23.56 152.45,23.91 152.46,23.91 152.63,24.04 152.69,24.24 152.59,24.49 152.33,24.6 152.23,24.6 151.95,24.88 151.95,26.15 152.28,26.15
N18867812 on TOP (solid shape): 20.43,31.57 20.51,31.36 20.68,31.23 20.71,31.21 20.71,30.06 20.86,29.91 20.9,29.87 20.94,29.83 21.07,29.7 21.4,29.7 21.53,29.57 21.53,28.93 21.68,28.79 21.68,28.71 21.68,28.57 21.66,28.53 21.63,28.52 20.91,28.52 20.91,28.32 21.63,28.32 21.66,28.3 21.68,28.27 21.68,28.17 21.66,28.13 21.63,28.12 20.91,28.12 20.91,28.1 20.88,28.07 20.09,28.07 19.95,28.21 18.96,28.21 18.86,28.31 18.83,28.38 18.86,28.45 18.88,28.49 18.89,28.54 18.89,29.91 18.86,30 18.77,30.03 18.71,30.03 18.71,31.16 18.71,31.16 18.71,31.56 18.76,31.61 20.43,31.61
N18922914 on TOP (solid shape): 100.94,110.18 100.97,110.15 101,110.12 101.1,110.02 101.1,108.88 100.13,107.9 100.1,107.89 100.06,107.9 99.99,107.95 99.91,107.96 99.61,107.96 99.49,107.93 99.4,107.84 99.4,107.82 99.37,107.81 97.52,107.81 97.24,108.09 97.24,108.47 97.39,108.62 98.41,108.62 98.49,108.7 98.49,108.72 98.54,108.81 98.65,108.8 98.75,108.74 98.87,108.72 99.22,109.08 98.87,109.44 98.83,109.43 98.77,109.46 98.79,109.52 98.8,109.54 98.86,109.61 98.9,109.68 98.92,109.71 98.94,109.71 99.88,109.71 99.96,109.79 99.98,109.79 100.12,109.85 100.18,110 100.19,110.02 100.39,110.22 100.9,110.22
N24742093 on BOTTOM (solid shape): 69.57,106.69 69.61,106.6 69.7,106.56 70.22,106.56 70.22,101.08 70.66,100.63 71.88,100.63 71.94,100.57 71.94,98.81 71.86,98.73 71.75,98.56 71.71,98.37 71.86,98.01 72.22,97.86 72.28,97.86 72.33,97.87 72.41,97.85 72.45,97.77 72.45,95.62 72.32,95.49 70.67,95.49 70.56,95.61 70.56,97.24 70.55,97.25 70.55,97.27 70.47,97.35 70.46,97.35 69.66,98.16 69.66,100.37 69.33,100.7 68.64,100.7 68.39,100.95 68.39,105.27 68.77,105.65 68.77,107.05 68.9,107.17 69.57,107.17
N24742107 on TOP (solid shape): 22.03,100.39 22.03,99.67 22.01,99.53 22.03,99.39 22.03,95.99 21.96,95.92 21.96,95.04 21.93,95.01 21.92,94.98 21.9,94.95 21.87,94.94 21.84,94.94 21.84,94.27 21.83,94.23 21.79,94.22 21.69,94.22 21.65,94.23 21.64,94.27 21.64,94.94 21.44,94.94 21.44,94.27 21.43,94.23 21.39,94.22 21.02,94.22 20.76,94.47 20.76,98.54 19.98,99.33 19.98,100.52 20.94,101.48
N28087213 on TOP (solid shape): 38.16,112.51 38.16,111.87 38.03,111.75 27.8,111.75 27.32,111.26 25.36,111.26 25.23,111.39 25.23,112.51 25.49,112.76 37.91,112.76
N28087213 on BOTTOM (solid shape): 25.87,112.61 25.87,111.64 24.74,110.79 23.44,110.14 20.81,109.08 18.86,109.08 18.48,109.46 18.48,110.73 19.75,112 20.03,112 20.74,111.29 21.42,110.93 21.8,110.93 23.36,111.71 23.96,112.13 24.62,112.79 25.69,112.79
N30319022 on TOP (solid shape): 140.54,77.94 140.55,77.93 140.56,77.52 140.58,77.45 140.62,77.41 140.64,77.4 140.65,77.38 140.65,77.2 140.93,76.92 142.12,76.92 142.71,76.34 142.71,74.74 142.4,74.43 137.45,74.43 137.15,74.74 137.15,76.44 137.7,77 138.64,77 138.72,77.08 138.72,77.68 139,77.96 140.52,77.96
N30319022 on BOTTOM (solid shape): 137.26,78.68 137.3,78.66 137.31,78.62 137.31,78.57 137.3,78.56 137.22,78.43 137.2,78.29 137.31,78.02 137.58,77.91 137.72,77.94 137.85,78.02 138.08,78.25 138.08,78.39 138.14,78.48 138.25,78.46 138.58,78.13 142.57,78.13 142.66,78.04 142.66,77.15 142.68,77.13 142.68,74.74 142.39,74.45 134.75,74.45 133.03,76.16 133.03,76.73 133.03,76.75 133.03,78.4 133.31,78.68
N30442035 on TOP (solid shape): 21.66,26.68 21.66,26.52 20.91,26.52 20.91,26.32 21.63,26.32 21.66,26.29 21.66,26.02 21.91,25.77 21.91,23.33 21.27,22.69 20.27,22.69 20.23,22.71 20.18,22.72 20.13,22.72 20.07,22.72 20.02,22.71 19.99,22.69 18.65,22.69 18.46,22.89 18.46,23.63 19.8,23.63 19.8,23.58 19.81,23.52 19.83,23.47 19.86,23.42 19.89,23.38 19.93,23.34 19.98,23.31 20.03,23.28 20.08,23.26 20.14,23.25 20.19,23.25 20.25,23.26 20.3,23.27 20.35,23.29 20.4,23.32 20.44,23.36 20.48,23.4 20.51,23.45 20.54,23.5 20.55,23.55 20.56,23.61 20.56,23.66 20.55,23.72 20.54,23.77 20.51,23.82 20.48,23.87 20.44,23.91 20.4,23.94 20.35,23.97 20.3,24 20.25,24.01 20.19,24.02 20.14,24.01 20.08,24 20.03,23.99 19.98,23.96 19.93,23.93 19.89,23.89 19.86,23.84 19.83,23.8 19.81,23.74 19.8,23.69 19.8,23.63 18.46,23.63 18.46,25.95 18.87,26.37 20.48,26.37 20.83,26.71 21.63,26.71
N31069510 on TOP (solid shape): 155.75,25.38 155.95,25.38 155.95,26.09 157.09,26.09 157.8,25.39 157.8,24.75 157.96,24.58 157.97,24.57 158.09,24.37 158.3,24.29 158.38,24.3 158.46,24.33 158.55,24.28 158.66,24.27 158.72,24.27 158.77,24.29 158.83,24.27 158.89,24.27 158.98,24.28 159.07,24.32 159.15,24.28 159.24,24.27 159.3,24.27 159.36,24.29 159.41,24.27 159.47,24.27 159.57,24.28 159.66,24.32 159.7,24.35 159.78,24.27 159.78,23 159.73,22.95 156.17,22.95 156.02,23.1 156.02,23.48 155.76,23.74 155.76,23.79 155.84,23.86 155.85,23.86 156.05,24 156.13,24.23 156.04,24.47 155.82,24.61 155.8,24.61 155.76,24.65 155.76,24.88 155.55,25.09 155.55,26.06 155.58,26.09 155.75,26.09
N31353058 on TOP (solid shape): outline of 105 points within 31.43,27.04 37.4,31.86
N35745545 on BOTTOM (solid shape): 128.99,40.18 129.59,40.18 129.66,40.12 129.66,39.39 129.59,39.32 128.7,39.32 127.59,40.44 127.37,40.44 127.2,40.61 127.2,41.27 127.32,41.39 127.78,41.39
N35745601 on BOTTOM (solid shape): 126.43,47.98 126.43,47.58 126.37,47.53 125.05,47.53 125.04,47.55 125.04,48.37 125.06,48.4 126.01,48.4
N35849315 on BOTTOM (solid shape): 101.73,57.67 101.73,56.83 101.71,56.81 100.87,56.81 100.6,56.53 100.6,54.66 100.22,54.28 100.22,52.7 98.21,50.7 97.63,50.7 97.2,51.13 97.2,51.99 97.22,52.06 97.23,52.13 97.23,52.15 97.32,52.25 97.71,52.25 97.76,52.2 97.76,51.81 97.76,51.34 97.76,51.28 97.88,51.15 98.23,51.15 98.28,51.2 98.28,51.2 99.74,52.66 99.74,52.67 99.74,54.61 100.07,54.94 100.07,57.36 100.42,57.72 101.68,57.72
N36953746 on TOP (solid shape): 52.41,22.44 52.41,22.06 52.23,21.88 51.65,21.88 51.5,21.73 51.5,20.74 50.84,20.08 50.4,20.08 50.25,20.23 50.25,20.81 50.61,21.17 50.61,22.53 50.64,22.54 50.73,22.59 50.8,22.67 52.18,22.67
N38517597 on TOP (solid shape): 15.79,14.06 16.74,14.06 16.84,13.96 16.84,13.45 16.95,13.33 16.95,12.56 16.83,12.43 16.44,12.43 16.19,12.69 15.3,12.69 15.05,12.94 15.05,14.07 15.17,14.2 15.66,14.2
N38517632 on TOP (solid shape): 21.6,17.46 21.6,17.33 21.5,17.24 21.5,15.74 21.42,15.66 20.25,15.66 20.18,15.73 20.18,17.54 21.52,17.54
N45198823 on TOP (solid shape): 61.59,125.6 61.59,123.77 61.38,123.56 60.21,123.56 59.95,123.82 59.95,124.13 59.78,124.3 59.77,124.3 59.75,124.32 59.09,124.32 58.86,124.55 58.86,125.74 59,125.89 61.3,125.89
N45198823 on BOTTOM (solid shape): 63.91,125.87 63.91,125.69 63.86,125.64 63.39,125.64 63.27,125.53 63.27,124.76 62.92,124.4 60.37,124.4 59.93,123.96 58.3,123.96 58.03,124.23 58.03,125.85 58.14,125.95 63.83,125.95
N47271970 on BOTTOM (solid shape): 96.71,88.76 96.71,88.51 95.97,87.77 95.97,87.16 95.92,87.11 95.62,87.11 94.35,88.38 93.38,88.38 93.28,88.48 93.28,88.89 96.58,88.89

Small or netless copper shapes (teardrops, artwork), in the pictures only: 76 on TOP, 80 on BOTTOM, 6 on IN1, 49 on IN2

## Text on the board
Ref Des/Silkscreen Bottom: Please do not print out the lines with 0.39mils/0.01mm in width | DAZAUIMB8C0  REV:C
User.Comments: 16x35 | 30x32 | 33x37
Ref Des/Silkscreen Top: Please do not print out the lines with 0.39mils/0.01mm in width | MODEL:ZAUI | DAZAUIMB8C0 REV:C
PAGE_OUTLINE: TOP HEIGHT | 6
BODY_CENTER: BOTTOM HEIGHT | BOTTOM COMPONENT | DFHS24FR477 | DFPJ03MR149 | DFHSR0FR008 | DFFC06FR198 | DFFC08FR055 | DFFC40FR090
User.6: TOP COMPONENT | 145 | 219.8 | 128
User.8: 145 | 219.8 | 128
User.9: DFHS24FR477 | DFPJ03MR149 | DFFC40FR090 | DFFC06FR198
User.12: GND | +3V_S5 | VA | +1.2VSUS | +3V | +5VPCU | +1.8V_S5 | +VGPU_CORE | +VCCIN | +VCCIN_AUX | +5V | +5V_S5 | ADOGND
User.25: 6
User.34: 1.1 | n | 1.6
User.36: GND | ADOGND
User.37: ADOGND | GND
